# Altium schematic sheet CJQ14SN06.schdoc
size 127 x 101 mm
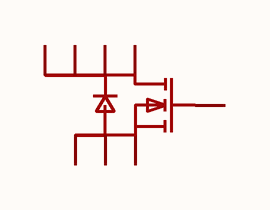
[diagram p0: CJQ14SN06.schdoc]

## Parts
Q?  cjq14sn06  [SOP-8_L4.9-W3.8-P1.27-LS6.0-BL]  (value not drawn)

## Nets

Not connected (* = marked no-connect by the designer): Q? 1(S) 2(S) 3(S) 4(G) 5(D) 6(D) 7(D) 8(D)

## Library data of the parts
Q? = cjq14sn06: 数量:1个N沟道;漏源电压(Vdss):60V;连续漏极电流(Id):14A;导通电阻(RDS(on)):9.7mΩ@10V;耗散功率(Pd):1.4W;阈值电压(Vgs(th)):2.5V;; Manufacturer: CJ(江苏长电/长晶); AddInBom: yes; ModelId: 0b80c7b2222d4c27a59de7b60fa3a3b4; ModelTransform: 192.913,236.22,0,0,0,0,0,0,0; Number: 1个N沟道; Drain to Source Voltage: 60V; Current - Continuous Drain(Id): 14A; Pd - Power Dissipation: 1.4W; Gate Threshold Voltage (Vgs(th)): 2.5V; Gate Charge(Qg): 39.8nC@10V; Input Capacitance(Ciss): 1.634nF; Reverse Transfer Capacitance (Crss@Vds): 11pF; Type: N沟道; Output Capacitance(Coss): 302pF; Vgs: ±20V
